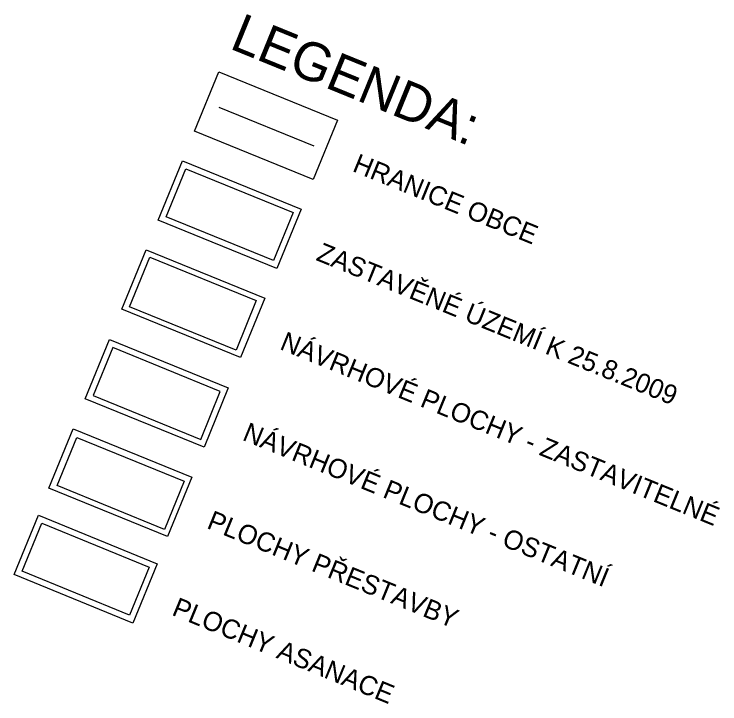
# Model space of a CAD drawing. Extents: x -520542 to -519991, y -1184606 to -1184068.
import ezdxf

# ---------------------------------------------------------------- set-up
doc = ezdxf.new("R2010")
doc.units = 0
for name, color, linetype in [('DOPRAVA', 7, 'Continuous'), ('hran_SZUO_P-s', 7, 'Continuous'), ('Implicitní', 7, 'Continuous'), ('zastavitelne plochy', 7, 'Continuous')]:
    doc.layers.add(name, color=color, linetype=linetype)

msp = doc.modelspace()

# ---------------------------------------------------------------- linework, layer by layer
at = {"layer": 'DOPRAVA'}
msp.add_lwpolyline([(-520467.37, -1184321.9), (-520374.78, -1184359.66), (-520393.66, -1184405.96), (-520486.26, -1184368.2)], close=True, dxfattribs=at)
at = {"layer": 'hran_SZUO_P-s'}
msp.add_lwpolyline([(-520407.87, -1184188.57), (-520324.07, -1184222.74), (-520339.36, -1184260.24), (-520423.16, -1184226.07)], close=True, dxfattribs=at)
at = {"layer": 'Implicitní'}
msp.add_line((-520382.08, -1184140.53), (-520308, -1184170.74), dxfattribs=at)
for points in [[(-520382.16, -1184112.93), (-520289.56, -1184150.69), (-520308.44, -1184196.99), (-520401.04, -1184159.23)], [(-520410.48, -1184182.38), (-520317.88, -1184220.14), (-520336.76, -1184266.44), (-520429.36, -1184228.68)], [(-520407.87, -1184188.57), (-520324.07, -1184222.74), (-520339.36, -1184260.24), (-520423.16, -1184226.07)], [(-520438.8, -1184251.82), (-520346.2, -1184289.59), (-520365.08, -1184335.88), (-520457.68, -1184298.12)], [(-520435.93, -1184257.45), (-520352.89, -1184291.31), (-520368.7, -1184330.09), (-520451.74, -1184296.22)], [(-520495.75, -1184391.48), (-520403.15, -1184429.24), (-520422.03, -1184475.54), (-520514.63, -1184437.78)], [(-520492.93, -1184398.3), (-520409.13, -1184432.47), (-520424.42, -1184469.97), (-520508.22, -1184435.8)], [(-520522.75, -1184458.94), (-520430.27, -1184496.98), (-520449.29, -1184543.23), (-520541.77, -1184505.18)], [(-520520.16, -1184465.14), (-520436.47, -1184499.57), (-520451.87, -1184537.03), (-520535.57, -1184502.6)]]:
    msp.add_lwpolyline(points, close=True, dxfattribs=at)
at = {"layer": 'zastavitelne plochy'}
msp.add_lwpolyline([(-520464.77, -1184328.1), (-520480.06, -1184365.6), (-520396.26, -1184399.77), (-520380.97, -1184362.27), (-520464.77, -1184328.1)], dxfattribs=at)

# ---------------------------------------------------------------- texts
at = {"layer": 'DOPRAVA'}
msp.add_text('NÁVRHOVÉ PLOCHY - OSTATNÍ', height=15, rotation=337.8143, dxfattribs=at).set_placement((-520364.47, -1184399.99))
at = {"layer": 'Implicitní'}
for s, height, rotation, p in [('LEGENDA:', 30, 337.8143, (-520374.6, -1184094.41)), ('HRANICE OBCE', 15, 337.8143, (-520278.68, -1184190.23)), ('ZASTAVĚNÉ ÚZEMÍ K 25.8.2009', 15, 337.8143, (-520307, -1184259.67)), ('NÁVRHOVÉ PLOCHY - ZASTAVITELNÉ', 15, 337.8143, (-520335.32, -1184329.12)), ('PLOCHY PŘESTAVBY', 15, 337.8143, (-520392.27, -1184468.77)), ('PLOCHY ASANACE', 15, 337.6408, (-520419.51, -1184536.55))]:
    msp.add_text(s, height=height, rotation=rotation, dxfattribs=at).set_placement(p)

doc.saveas('drawing.dxf')
